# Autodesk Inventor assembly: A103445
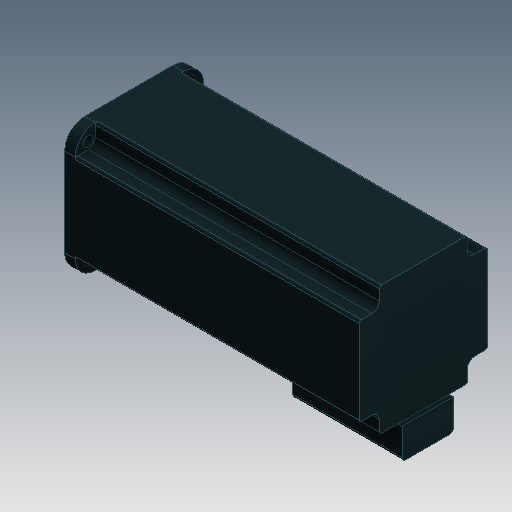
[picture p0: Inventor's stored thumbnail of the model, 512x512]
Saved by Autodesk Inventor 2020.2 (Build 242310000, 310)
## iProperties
Created: 1999-12
Part Number: A103445
Description: MOTOR,SERVO W/BRAKE
Document SubType Name: Assembly
Designer: sspink
Mass: 25990.9 g
Surface Area: 1550.85 cm^2
Volume: 3319.4 cm^3
Density: 7.83 g/cm^3
Control State: 0
Checked Out: False
Master: False
Shininess: 0.0
Length Units: 11272
Angle Units: 11279
Time Units: 11290
Mass Units: 11286
Length Display Precision: 3
Angle Display Precision: 2
Compacted: True
Dimensions: 5,6x4,5x12,1 in
Mass: 57,3 lb
Density: 0.0
Volumn: 0.0
Area: 0.0
PropertySet Name: Model Information
Author: sspink
Revision Number: -
Title: MOTOR,SERVO W/BRAKE
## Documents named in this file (3)
- D:\07 - DEMODATEN\OTX 2019 - Dataset - UPDATE - Dez2019\Designs\07-Packing machine\A103445.iam
- D:\07 - DEMODATEN\OTX 2019 - Dataset - UPDATE - Dez2019\Designs\07-Packing machine\Parts\ADSK-011377.ipt
- D:\07 - DEMODATEN\OTX 2019 - Dataset - UPDATE - Dez2019\Designs\07-Packing machine\Parts\ADSK-011376.ipt
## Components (2 placed, 2 different names)
1. ADSK-011376:1 — Flush:1, Flush:2, Flush:3, Mate:1, Mate:2
2. ADSK-011377:1 — Mate:1, Mate:2
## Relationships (5: Flush 3, Mate 2)
- Flush:1: ADSK-011376:1
- Flush:2: ADSK-011376:1
- Flush:3: ADSK-011376:1
- Mate:1: ADSK-011376:1 ↔ ADSK-011377:1
- Mate:2: ADSK-011376:1 ↔ ADSK-011377:1
